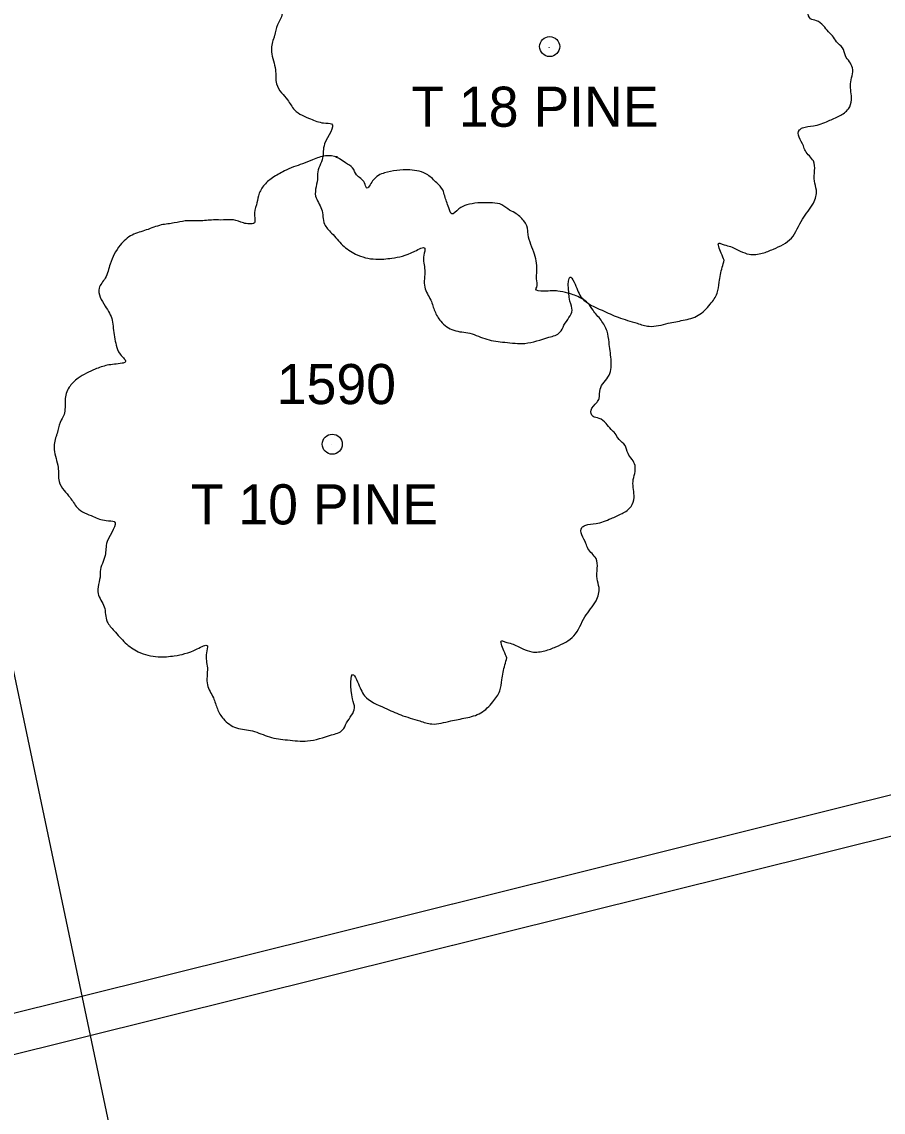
# Model space of a CAD drawing. Extents: x 1964982 to 1970452, y 1116335 to 1119906.
# Drawn here: x 1966676.88 to 1966698.37, y 1117449.81 to 1117477 of the extents above; entities that cross this region are included whole.
import ezdxf

# ---------------------------------------------------------------- set-up
doc = ezdxf.new("R2010")
doc.units = 0
for name, color, linetype in [('RD_EX_VEG', 7, 'Continuous'), ('RD_EX_VEG_txCode', 7, 'Continuous'), ('RD_HC_CL_Rel', 7, 'Continuous'), ('RD_HC_Data', 7, 'Continuous'), ('RD_PD_CstnLmt', 7, 'Continuous'), ('RD_PD_Final_TrvlWay', 7, 'Continuous'), ('RD_PD_RW', 7, 'Continuous')]:
    doc.layers.add(name, color=color, linetype=linetype)

msp = doc.modelspace()

# ---------------------------------------------------------------- linework, layer by layer
at = {"layer": 'RD_EX_VEG'}
for centre, radius in [((1966690.05, 1117476.387), 0.25), ((1966690.05, 1117476.387), 0.25), ((1966690.038, 1117476.368), 0.0001), ((1966690.038, 1117476.368), 0.0001), ((1966684.627, 1117466.469), 0.25), ((1966684.627, 1117466.469), 0.25), ((1966684.614, 1117466.45), 0.0001), ((1966684.614, 1117466.45), 0.0001)]:
    msp.add_circle(centre, radius, dxfattribs=at)
for points in [[(1966690.182, 1117483.554), (1966689.882, 1117483.579), (1966689.558, 1117483.479), (1966689.308, 1117483.379), (1966689.083, 1117483.304), (1966688.858, 1117483.204), (1966688.558, 1117483.029), (1966688.333, 1117482.829), (1966688.208, 1117482.579), (1966688.158, 1117482.355), (1966688.108, 1117482.08), (1966688.108, 1117481.905), (1966687.983, 1117481.88), (1966687.833, 1117481.905), (1966687.583, 1117481.98), (1966687.333, 1117481.98), (1966687.084, 1117481.98), (1966686.734, 1117481.955), (1966686.384, 1117481.955), (1966686.109, 1117481.905), (1966685.784, 1117481.855), (1966685.409, 1117481.73), (1966685.059, 1117481.605), (1966684.76, 1117481.355), (1966684.51, 1117480.88), (1966684.385, 1117480.53), (1966684.235, 1117480.28), (1966684.385, 1117479.831), (1966684.56, 1117479.481), (1966684.585, 1117479.281), (1966684.66, 1117478.856), (1966684.76, 1117478.631), (1966684.885, 1117478.431), (1966684.81, 1117478.406), (1966684.435, 1117478.356), (1966684.135, 1117478.256), (1966683.71, 1117478.031), (1966683.485, 1117477.807), (1966683.385, 1117477.482), (1966683.36, 1117477.132), (1966683.26, 1117476.932), (1966683.185, 1117476.657), (1966683.16, 1117476.582), (1966683.11, 1117476.257), (1966683.21, 1117475.807), (1966683.235, 1117475.458), (1966683.36, 1117475.233), (1966683.51, 1117475.058), (1966683.685, 1117474.808), (1966684.085, 1117474.583), (1966684.41, 1117474.483), (1966684.61, 1117474.458), (1966684.435, 1117473.958), (1966684.385, 1117473.608), (1966684.26, 1117473.209), (1966684.26, 1117473.134), (1966684.21, 1117472.659), (1966684.36, 1117472.334), (1966684.435, 1117471.959), (1966684.61, 1117471.734), (1966684.885, 1117471.434), (1966685.209, 1117471.209), (1966685.709, 1117471.084), (1966686.109, 1117471.109), (1966686.684, 1117471.284), (1966686.934, 1117471.359), (1966686.909, 1117471.184), (1966686.934, 1117470.81), (1966686.934, 1117470.385), (1966687.084, 1117470.06), (1966687.184, 1117469.785), (1966687.333, 1117469.535), (1966687.658, 1117469.31), (1966688.058, 1117469.235), (1966688.483, 1117469.085), (1966688.933, 1117469.01), (1966689.433, 1117468.985), (1966690.032, 1117469.135), (1966690.307, 1117469.26), (1966690.407, 1117469.435), (1966690.607, 1117469.81), (1966690.557, 1117470.035), (1966690.582, 1117470.635), (1966690.682, 1117470.46), (1966690.857, 1117470.11), (1966691.357, 1117469.81), (1966691.757, 1117469.635), (1966692.231, 1117469.485), (1966692.531, 1117469.41), (1966693.006, 1117469.485), (1966693.381, 1117469.56), (1966693.756, 1117469.685), (1966694.056, 1117469.96), (1966694.23, 1117470.235), (1966694.28, 1117470.51), (1966694.355, 1117470.885), (1966694.405, 1117471.059)], [(1966690.182, 1117483.554), (1966689.882, 1117483.579), (1966689.558, 1117483.479), (1966689.308, 1117483.379), (1966689.083, 1117483.304), (1966688.858, 1117483.204), (1966688.558, 1117483.029), (1966688.333, 1117482.829), (1966688.208, 1117482.579), (1966688.158, 1117482.355), (1966688.108, 1117482.08), (1966688.108, 1117481.905), (1966687.983, 1117481.88), (1966687.833, 1117481.905), (1966687.583, 1117481.98), (1966687.333, 1117481.98), (1966687.084, 1117481.98), (1966686.734, 1117481.955), (1966686.384, 1117481.955), (1966686.109, 1117481.905), (1966685.784, 1117481.855), (1966685.409, 1117481.73), (1966685.059, 1117481.605), (1966684.76, 1117481.355), (1966684.51, 1117480.88), (1966684.385, 1117480.53), (1966684.235, 1117480.28), (1966684.385, 1117479.831), (1966684.56, 1117479.481), (1966684.585, 1117479.281), (1966684.66, 1117478.856), (1966684.76, 1117478.631), (1966684.885, 1117478.431), (1966684.81, 1117478.406), (1966684.435, 1117478.356), (1966684.135, 1117478.256), (1966683.71, 1117478.031), (1966683.485, 1117477.807), (1966683.385, 1117477.482), (1966683.36, 1117477.132), (1966683.26, 1117476.932), (1966683.185, 1117476.657), (1966683.16, 1117476.582), (1966683.11, 1117476.257), (1966683.21, 1117475.807), (1966683.235, 1117475.458), (1966683.36, 1117475.233), (1966683.51, 1117475.058), (1966683.685, 1117474.808), (1966684.085, 1117474.583), (1966684.41, 1117474.483), (1966684.61, 1117474.458), (1966684.435, 1117473.958), (1966684.385, 1117473.608), (1966684.26, 1117473.209), (1966684.26, 1117473.134), (1966684.21, 1117472.659), (1966684.36, 1117472.334), (1966684.435, 1117471.959), (1966684.61, 1117471.734), (1966684.885, 1117471.434), (1966685.209, 1117471.209), (1966685.709, 1117471.084), (1966686.109, 1117471.109), (1966686.684, 1117471.284), (1966686.934, 1117471.359), (1966686.909, 1117471.184), (1966686.934, 1117470.81), (1966686.934, 1117470.385), (1966687.084, 1117470.06), (1966687.184, 1117469.785), (1966687.333, 1117469.535), (1966687.658, 1117469.31), (1966688.058, 1117469.235), (1966688.483, 1117469.085), (1966688.933, 1117469.01), (1966689.433, 1117468.985), (1966690.032, 1117469.135), (1966690.307, 1117469.26), (1966690.407, 1117469.435), (1966690.607, 1117469.81), (1966690.557, 1117470.035), (1966690.582, 1117470.635), (1966690.682, 1117470.46), (1966690.857, 1117470.11), (1966691.357, 1117469.81), (1966691.757, 1117469.635), (1966692.231, 1117469.485), (1966692.531, 1117469.41), (1966693.006, 1117469.485), (1966693.381, 1117469.56), (1966693.756, 1117469.685), (1966694.056, 1117469.96), (1966694.23, 1117470.235), (1966694.28, 1117470.51), (1966694.355, 1117470.885), (1966694.405, 1117471.059)], [(1966694.405, 1117471.059), (1966694.33, 1117471.234), (1966694.28, 1117471.484), (1966694.355, 1117471.459), (1966694.53, 1117471.409), (1966694.805, 1117471.284), (1966695.03, 1117471.209), (1966695.355, 1117471.234), (1966695.63, 1117471.334), (1966696.08, 1117471.609), (1966696.355, 1117472.084), (1966696.629, 1117472.484), (1966696.704, 1117472.809), (1966696.654, 1117473.034), (1966696.629, 1117473.533), (1966696.429, 1117473.783), (1966696.379, 1117473.908), (1966696.28, 1117474.308), (1966696.355, 1117474.358), (1966696.629, 1117474.408), (1966697.004, 1117474.533), (1966697.279, 1117474.658), (1966697.504, 1117474.833), (1966697.579, 1117475.058), (1966697.554, 1117475.458), (1966697.604, 1117475.857), (1966697.529, 1117476.007), (1966697.429, 1117476.157), (1966697.354, 1117476.357), (1966697.204, 1117476.507), (1966697.104, 1117476.657), (1966697.004, 1117476.757), (1966696.879, 1117476.907), (1966696.704, 1117477.032), (1966696.554, 1117477.082), (1966696.504, 1117477.232), (1966696.654, 1117477.432), (1966696.704, 1117477.532), (1966696.729, 1117477.757), (1966696.954, 1117478.106), (1966697.004, 1117478.506), (1966696.954, 1117478.931), (1966696.904, 1117479.206), (1966696.754, 1117479.481), (1966696.554, 1117479.731), (1966696.429, 1117479.906), (1966696.255, 1117480.031), (1966695.93, 1117480.156), (1966695.68, 1117480.205), (1966695.33, 1117480.205), (1966695.13, 1117480.255), (1966695.155, 1117480.305), (1966695.155, 1117480.455), (1966695.155, 1117480.73), (1966695.08, 1117481.18), (1966694.93, 1117481.68), (1966694.93, 1117481.705), (1966694.83, 1117481.955), (1966694.605, 1117482.155), (1966694.43, 1117482.255), (1966694.23, 1117482.38), (1966693.981, 1117482.405), (1966693.681, 1117482.405), (1966693.406, 1117482.355), (1966693.206, 1117482.255), (1966693.031, 1117482.13), (1966692.956, 1117482.28), (1966692.856, 1117482.579), (1966692.806, 1117482.729), (1966692.656, 1117482.904), (1966692.431, 1117483.104), (1966691.981, 1117483.229), (1966691.357, 1117483.154), (1966691.057, 1117482.954), (1966690.907, 1117482.779), (1966690.857, 1117482.904), (1966690.657, 1117483.104), (1966690.557, 1117483.279), (1966690.382, 1117483.404), (1966690.232, 1117483.504), (1966690.132, 1117483.554)], [(1966694.405, 1117471.059), (1966694.33, 1117471.234), (1966694.28, 1117471.484), (1966694.355, 1117471.459), (1966694.53, 1117471.409), (1966694.805, 1117471.284), (1966695.03, 1117471.209), (1966695.355, 1117471.234), (1966695.63, 1117471.334), (1966696.08, 1117471.609), (1966696.355, 1117472.084), (1966696.629, 1117472.484), (1966696.704, 1117472.809), (1966696.654, 1117473.034), (1966696.629, 1117473.533), (1966696.429, 1117473.783), (1966696.379, 1117473.908), (1966696.28, 1117474.308), (1966696.355, 1117474.358), (1966696.629, 1117474.408), (1966697.004, 1117474.533), (1966697.279, 1117474.658), (1966697.504, 1117474.833), (1966697.579, 1117475.058), (1966697.554, 1117475.458), (1966697.604, 1117475.857), (1966697.529, 1117476.007), (1966697.429, 1117476.157), (1966697.354, 1117476.357), (1966697.204, 1117476.507), (1966697.104, 1117476.657), (1966697.004, 1117476.757), (1966696.879, 1117476.907), (1966696.704, 1117477.032), (1966696.554, 1117477.082), (1966696.504, 1117477.232), (1966696.654, 1117477.432), (1966696.704, 1117477.532), (1966696.729, 1117477.757), (1966696.954, 1117478.106), (1966697.004, 1117478.506), (1966696.954, 1117478.931), (1966696.904, 1117479.206), (1966696.754, 1117479.481), (1966696.554, 1117479.731), (1966696.429, 1117479.906), (1966696.255, 1117480.031), (1966695.93, 1117480.156), (1966695.68, 1117480.205), (1966695.33, 1117480.205), (1966695.13, 1117480.255), (1966695.155, 1117480.305), (1966695.155, 1117480.455), (1966695.155, 1117480.73), (1966695.08, 1117481.18), (1966694.93, 1117481.68), (1966694.93, 1117481.705), (1966694.83, 1117481.955), (1966694.605, 1117482.155), (1966694.43, 1117482.255), (1966694.23, 1117482.38), (1966693.981, 1117482.405), (1966693.681, 1117482.405), (1966693.406, 1117482.355), (1966693.206, 1117482.255), (1966693.031, 1117482.13), (1966692.956, 1117482.28), (1966692.856, 1117482.579), (1966692.806, 1117482.729), (1966692.656, 1117482.904), (1966692.431, 1117483.104), (1966691.981, 1117483.229), (1966691.357, 1117483.154), (1966691.057, 1117482.954), (1966690.907, 1117482.779), (1966690.857, 1117482.904), (1966690.657, 1117483.104), (1966690.557, 1117483.279), (1966690.382, 1117483.404), (1966690.232, 1117483.504), (1966690.132, 1117483.554)], [(1966684.758, 1117473.636), (1966684.459, 1117473.661), (1966684.134, 1117473.561), (1966683.884, 1117473.461), (1966683.659, 1117473.386), (1966683.434, 1117473.286), (1966683.134, 1117473.111), (1966682.909, 1117472.911), (1966682.784, 1117472.661), (1966682.734, 1117472.436), (1966682.684, 1117472.162), (1966682.684, 1117471.987), (1966682.559, 1117471.962), (1966682.409, 1117471.987), (1966682.16, 1117472.062), (1966681.91, 1117472.062), (1966681.66, 1117472.062), (1966681.31, 1117472.037), (1966680.96, 1117472.037), (1966680.685, 1117471.987), (1966680.36, 1117471.937), (1966679.986, 1117471.812), (1966679.636, 1117471.687), (1966679.336, 1117471.437), (1966679.086, 1117470.962), (1966678.961, 1117470.612), (1966678.811, 1117470.362), (1966678.961, 1117469.913), (1966679.136, 1117469.563), (1966679.161, 1117469.363), (1966679.236, 1117468.938), (1966679.336, 1117468.713), (1966679.461, 1117468.513), (1966679.386, 1117468.488), (1966679.011, 1117468.438), (1966678.711, 1117468.338), (1966678.286, 1117468.113), (1966678.061, 1117467.888), (1966677.961, 1117467.563), (1966677.936, 1117467.214), (1966677.837, 1117467.014), (1966677.762, 1117466.739), (1966677.737, 1117466.664), (1966677.687, 1117466.339), (1966677.787, 1117465.889), (1966677.812, 1117465.539), (1966677.936, 1117465.314), (1966678.086, 1117465.14), (1966678.261, 1117464.89), (1966678.661, 1117464.665), (1966678.986, 1117464.565), (1966679.186, 1117464.54), (1966679.011, 1117464.04), (1966678.961, 1117463.69), (1966678.836, 1117463.29), (1966678.836, 1117463.215), (1966678.786, 1117462.741), (1966678.936, 1117462.416), (1966679.011, 1117462.041), (1966679.186, 1117461.816), (1966679.461, 1117461.516), (1966679.786, 1117461.291), (1966680.285, 1117461.166), (1966680.685, 1117461.191), (1966681.26, 1117461.366), (1966681.51, 1117461.441), (1966681.485, 1117461.266), (1966681.51, 1117460.891), (1966681.51, 1117460.467), (1966681.66, 1117460.142), (1966681.76, 1117459.867), (1966681.91, 1117459.617), (1966682.235, 1117459.392), (1966682.634, 1117459.317), (1966683.059, 1117459.167), (1966683.509, 1117459.092), (1966684.009, 1117459.067), (1966684.609, 1117459.217), (1966684.883, 1117459.342), (1966684.983, 1117459.517), (1966685.183, 1117459.892), (1966685.133, 1117460.117), (1966685.158, 1117460.717), (1966685.258, 1117460.542), (1966685.433, 1117460.192), (1966685.933, 1117459.892), (1966686.333, 1117459.717), (1966686.808, 1117459.567), (1966687.107, 1117459.492), (1966687.582, 1117459.567), (1966687.957, 1117459.642), (1966688.332, 1117459.767), (1966688.632, 1117460.042), (1966688.807, 1117460.317), (1966688.857, 1117460.592), (1966688.932, 1117460.966), (1966688.982, 1117461.141)], [(1966684.758, 1117473.636), (1966684.459, 1117473.661), (1966684.134, 1117473.561), (1966683.884, 1117473.461), (1966683.659, 1117473.386), (1966683.434, 1117473.286), (1966683.134, 1117473.111), (1966682.909, 1117472.911), (1966682.784, 1117472.661), (1966682.734, 1117472.436), (1966682.684, 1117472.162), (1966682.684, 1117471.987), (1966682.559, 1117471.962), (1966682.409, 1117471.987), (1966682.16, 1117472.062), (1966681.91, 1117472.062), (1966681.66, 1117472.062), (1966681.31, 1117472.037), (1966680.96, 1117472.037), (1966680.685, 1117471.987), (1966680.36, 1117471.937), (1966679.986, 1117471.812), (1966679.636, 1117471.687), (1966679.336, 1117471.437), (1966679.086, 1117470.962), (1966678.961, 1117470.612), (1966678.811, 1117470.362), (1966678.961, 1117469.913), (1966679.136, 1117469.563), (1966679.161, 1117469.363), (1966679.236, 1117468.938), (1966679.336, 1117468.713), (1966679.461, 1117468.513), (1966679.386, 1117468.488), (1966679.011, 1117468.438), (1966678.711, 1117468.338), (1966678.286, 1117468.113), (1966678.061, 1117467.888), (1966677.961, 1117467.563), (1966677.936, 1117467.214), (1966677.837, 1117467.014), (1966677.762, 1117466.739), (1966677.737, 1117466.664), (1966677.687, 1117466.339), (1966677.787, 1117465.889), (1966677.812, 1117465.539), (1966677.936, 1117465.314), (1966678.086, 1117465.14), (1966678.261, 1117464.89), (1966678.661, 1117464.665), (1966678.986, 1117464.565), (1966679.186, 1117464.54), (1966679.011, 1117464.04), (1966678.961, 1117463.69), (1966678.836, 1117463.29), (1966678.836, 1117463.215), (1966678.786, 1117462.741), (1966678.936, 1117462.416), (1966679.011, 1117462.041), (1966679.186, 1117461.816), (1966679.461, 1117461.516), (1966679.786, 1117461.291), (1966680.285, 1117461.166), (1966680.685, 1117461.191), (1966681.26, 1117461.366), (1966681.51, 1117461.441), (1966681.485, 1117461.266), (1966681.51, 1117460.891), (1966681.51, 1117460.467), (1966681.66, 1117460.142), (1966681.76, 1117459.867), (1966681.91, 1117459.617), (1966682.235, 1117459.392), (1966682.634, 1117459.317), (1966683.059, 1117459.167), (1966683.509, 1117459.092), (1966684.009, 1117459.067), (1966684.609, 1117459.217), (1966684.883, 1117459.342), (1966684.983, 1117459.517), (1966685.183, 1117459.892), (1966685.133, 1117460.117), (1966685.158, 1117460.717), (1966685.258, 1117460.542), (1966685.433, 1117460.192), (1966685.933, 1117459.892), (1966686.333, 1117459.717), (1966686.808, 1117459.567), (1966687.107, 1117459.492), (1966687.582, 1117459.567), (1966687.957, 1117459.642), (1966688.332, 1117459.767), (1966688.632, 1117460.042), (1966688.807, 1117460.317), (1966688.857, 1117460.592), (1966688.932, 1117460.966), (1966688.982, 1117461.141)], [(1966688.982, 1117461.141), (1966688.907, 1117461.316), (1966688.857, 1117461.566), (1966688.932, 1117461.541), (1966689.107, 1117461.491), (1966689.381, 1117461.366), (1966689.606, 1117461.291), (1966689.931, 1117461.316), (1966690.206, 1117461.416), (1966690.656, 1117461.691), (1966690.931, 1117462.166), (1966691.206, 1117462.566), (1966691.281, 1117462.891), (1966691.231, 1117463.115), (1966691.206, 1117463.615), (1966691.006, 1117463.865), (1966690.956, 1117463.99), (1966690.856, 1117464.39), (1966690.931, 1117464.44), (1966691.206, 1117464.49), (1966691.58, 1117464.615), (1966691.855, 1117464.74), (1966692.08, 1117464.915), (1966692.155, 1117465.14), (1966692.13, 1117465.539), (1966692.18, 1117465.939), (1966692.105, 1117466.089), (1966692.005, 1117466.239), (1966691.93, 1117466.439), (1966691.78, 1117466.589), (1966691.68, 1117466.739), (1966691.58, 1117466.839), (1966691.456, 1117466.989), (1966691.281, 1117467.114), (1966691.131, 1117467.164), (1966691.081, 1117467.314), (1966691.231, 1117467.514), (1966691.281, 1117467.613), (1966691.306, 1117467.838), (1966691.531, 1117468.188), (1966691.58, 1117468.588), (1966691.531, 1117469.013), (1966691.481, 1117469.288), (1966691.331, 1117469.563), (1966691.131, 1117469.813), (1966691.006, 1117469.987), (1966690.831, 1117470.112), (1966690.506, 1117470.237), (1966690.256, 1117470.287), (1966689.906, 1117470.287), (1966689.706, 1117470.337), (1966689.731, 1117470.387), (1966689.731, 1117470.537), (1966689.731, 1117470.812), (1966689.656, 1117471.262), (1966689.506, 1117471.762), (1966689.506, 1117471.787), (1966689.406, 1117472.037), (1966689.182, 1117472.236), (1966689.007, 1117472.336), (1966688.807, 1117472.461), (1966688.557, 1117472.486), (1966688.257, 1117472.486), (1966687.982, 1117472.436), (1966687.782, 1117472.336), (1966687.607, 1117472.211), (1966687.532, 1117472.361), (1966687.432, 1117472.661), (1966687.382, 1117472.811), (1966687.232, 1117472.986), (1966687.008, 1117473.186), (1966686.558, 1117473.311), (1966685.933, 1117473.236), (1966685.633, 1117473.036), (1966685.483, 1117472.861), (1966685.433, 1117472.986), (1966685.233, 1117473.186), (1966685.133, 1117473.361), (1966684.958, 1117473.486), (1966684.808, 1117473.586), (1966684.708, 1117473.636)], [(1966688.982, 1117461.141), (1966688.907, 1117461.316), (1966688.857, 1117461.566), (1966688.932, 1117461.541), (1966689.107, 1117461.491), (1966689.381, 1117461.366), (1966689.606, 1117461.291), (1966689.931, 1117461.316), (1966690.206, 1117461.416), (1966690.656, 1117461.691), (1966690.931, 1117462.166), (1966691.206, 1117462.566), (1966691.281, 1117462.891), (1966691.231, 1117463.115), (1966691.206, 1117463.615), (1966691.006, 1117463.865), (1966690.956, 1117463.99), (1966690.856, 1117464.39), (1966690.931, 1117464.44), (1966691.206, 1117464.49), (1966691.58, 1117464.615), (1966691.855, 1117464.74), (1966692.08, 1117464.915), (1966692.155, 1117465.14), (1966692.13, 1117465.539), (1966692.18, 1117465.939), (1966692.105, 1117466.089), (1966692.005, 1117466.239), (1966691.93, 1117466.439), (1966691.78, 1117466.589), (1966691.68, 1117466.739), (1966691.58, 1117466.839), (1966691.456, 1117466.989), (1966691.281, 1117467.114), (1966691.131, 1117467.164), (1966691.081, 1117467.314), (1966691.231, 1117467.514), (1966691.281, 1117467.613), (1966691.306, 1117467.838), (1966691.531, 1117468.188), (1966691.58, 1117468.588), (1966691.531, 1117469.013), (1966691.481, 1117469.288), (1966691.331, 1117469.563), (1966691.131, 1117469.813), (1966691.006, 1117469.987), (1966690.831, 1117470.112), (1966690.506, 1117470.237), (1966690.256, 1117470.287), (1966689.906, 1117470.287), (1966689.706, 1117470.337), (1966689.731, 1117470.387), (1966689.731, 1117470.537), (1966689.731, 1117470.812), (1966689.656, 1117471.262), (1966689.506, 1117471.762), (1966689.506, 1117471.787), (1966689.406, 1117472.037), (1966689.182, 1117472.236), (1966689.007, 1117472.336), (1966688.807, 1117472.461), (1966688.557, 1117472.486), (1966688.257, 1117472.486), (1966687.982, 1117472.436), (1966687.782, 1117472.336), (1966687.607, 1117472.211), (1966687.532, 1117472.361), (1966687.432, 1117472.661), (1966687.382, 1117472.811), (1966687.232, 1117472.986), (1966687.008, 1117473.186), (1966686.558, 1117473.311), (1966685.933, 1117473.236), (1966685.633, 1117473.036), (1966685.483, 1117472.861), (1966685.433, 1117472.986), (1966685.233, 1117473.186), (1966685.133, 1117473.361), (1966684.958, 1117473.486), (1966684.808, 1117473.586), (1966684.708, 1117473.636)]]:
    msp.add_spline(points, degree=3, dxfattribs=at)
at = {"layer": 'RD_HC_CL_Rel'}
msp.add_arc((1966373.74, 1118527.456), 1145.915, 281.904723, 295.046328, dxfattribs=at)
at = {"layer": 'RD_HC_Data'}
msp.add_line((1966684.871, 1117421.945), (1966664.447, 1117518.825), dxfattribs=at)
at = {"layer": 'RD_PD_CstnLmt'}
msp.add_line((1966714.573, 1117460.668), (1966667.156, 1117448.875), dxfattribs=at)
at = {"layer": 'RD_PD_Final_TrvlWay'}
for radius in [1134.915, 1156.915]:
    msp.add_arc((1966373.74, 1118527.456), radius, 281.904723, 295.046328, dxfattribs=at)
at = {"layer": 'RD_PD_RW'}
msp.add_line((1966714.309, 1117461.633), (1966666.917, 1117449.846), dxfattribs=at)

# ---------------------------------------------------------------- texts
at = {"layer": 'RD_EX_VEG_txCode'}
for s, p in [('T 18 PINE', (1966686.598, 1117474.387)), ('T 18 PINE', (1966686.598, 1117474.387)), ('1590', (1966683.241, 1117467.469)), ('1590', (1966683.241, 1117467.469)), ('T 10 PINE', (1966681.095, 1117464.469)), ('T 10 PINE', (1966681.095, 1117464.469))]:
    msp.add_text(s, height=1, dxfattribs=at).set_placement(p)

doc.saveas('drawing.dxf')
